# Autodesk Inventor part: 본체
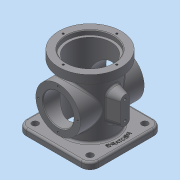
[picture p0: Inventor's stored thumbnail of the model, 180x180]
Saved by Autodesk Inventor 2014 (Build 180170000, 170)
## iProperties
Created: 2021-03
Part Number: 본체
Material: 일반
Document SubType Name: Modeling
Designer: net
Density: 1 g/cm^3
Appearance: 기본값
Author: net
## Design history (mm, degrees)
sketch "스케치1"
  geometry: L1 (-57, 57)-(57, 57); L2 (57, 57)-(57, -57); L3 (57, -57)-(-57, -57); L4 (-57, -57)-(-57, 57); 3 further points
  constraints: 8 end point, 2 midpoint, 2 parallel, 2 perpendicular, 1 horizontal, 1 horizontal alignment, 1 vertical alignment
  dimensions: "d0" = 114 distance of L3.end L1.start
extrude "돌출1" new body sketch "스케치1" distance "d1" = 10; taper "d2" = 0 deg
sketch "스케치2"
  geometry: L1 (57, 10)-(-57, 10) reference; L2 (49, 111)-(49, 98); L3 (49, 98)-(38, 98); L4 (38, 98)-(38, 10); L5 (33, 10)-(33, 104); L6 (33, 104)-(37, 104); L7 (37, 104)-(37, 111); L8 (0, 111)-(0, 10); L9 (49, 111)-(0, 111); L10 (-57, 0)-(57, 0) reference; L11 (38, 10)-(0, 10); 1 further point
  constraints: 18 end point, 3 point on line, 2 perpendicular, 1 collinear, 1 midpoint, 1 vertical alignment
  dimensions: "d4" = 7 distance between parallel lines of L6 L9; "d5" = 13 distance between parallel lines of L9 L3; "d6" = 98 diameter of L2 L8; "d7" = 74 diameter of L7 L8; "d8" = 66 diameter of L5 L8; "d9" = 76 diameter of L4 L8; "d11" = 104 distance between parallel lines of L10 L6
revolve "회전1" sketch "스케치2" stored, may be unused: angle "d10" = 90 deg
sketch "스케치3"
  geometry: L1 (-61.35, 54)-(61.35, 54); L2 (-57, 0)-(57, 0) reference; L3 (-50, 54)-(-50, 78); L4 (-50, 78)-(50, 78); L5 (50, 78)-(50, 54); L6 (50, 78)-(50, 89); L7 (50, 89)-(-50, 89); L8 (-50, 89)-(-50, 78); 4 further points
  constraints: 14 end point, 3 midpoint, 3 perpendicular, 2 parallel, 2 point on line, 2 vertical alignment, 1 collinear, 1 horizontal
  dimensions: "d12" = 54 distance between parallel lines of L2 L1; "d13" = 48 diameter of L4 L1; "d14" = 70 diameter of L7 L1; "d15" = 50 distance from line of L3 point (0, 54)
revolve "회전2" stored, may be unused: angle "d16" = 90 deg
revolve "회전3" stored, may be unused: angle "d17" = 90 deg
node "작업 평면1"
sketch "스케치4"
  geometry: L1 (0, 70)-(0, 41); L2 (-7, 70)-(-7, 41); L3 (7, 41)-(7, 70); L4 (0, 77)-(18.274, 77); L5 (0, 34)-(18.274, 34); L6 (0, 55.5)-(16.933, 55.5); L7 (-50, 30)-(-50, 78) reference; L8 (57, 0)-(-57, 0) reference; A1 r 7 centre (0, 70) between (7, 70) and (-7, 70); A2 r 7 centre (0, 41) between (-7, 41) and (7, 41); 3 further points
  constraints: 14 end point, 6 point on circle, 6 tangent, 3 midpoint, 3 parallel, 2 centre point, 1 perpendicular, 1 vertical, 1 vertical alignment
  dimensions: "d19" = 43 distance between parallel lines of L5 L4; "d20" = 20 vertical distance of L5.start point (-50, 54); "d21" = 14 distance between parallel lines of L3 L2
extrude "돌출2" join sketch "스케치4" stored distance "d22" = 10; taper "d23" = 15 deg
sketch "스케치5"
  geometry: C1 r 24 at (0, 0) reference; 2 further points
  constraints: 1 vertical alignment
hole "구멍1" sketch "스케치5" at (0, 31) diameter "d25" = 3.242; stored, may be unused: countersink angle "d29" = 90 deg, drill point angle "d31" = 118 deg; dims "d26" = 6, "d27" = 4, "d28" = 2, "d30" = 8
sketch "스케치6"
  geometry: C1 r 33 at (0, 0) reference
extrude "돌출3" cut sketch "스케치6" stored distance "d35" = 10; taper "d36" = 0 deg
fillet "모깎기1" dims "d37" = 14
sketch "스케치7"
  geometry: 1 further point
hole "구멍2" sketch "스케치7" at (0, 42) diameter "d39" = 3.242; stored, may be unused: countersink angle "d43" = 90 deg, drill point angle "d45" = 118 deg; dims "d40" = 6, "d41" = 4, "d42" = 2, "d44" = 8
sketch "스케치8"
  geometry: A1 r 7 centre (-41, 0) between (-41, -7) and (-41, 7) reference; A2 r 7 centre (-70, 0) between (-70, 7) and (-70, -7) reference; 1 further point
hole "구멍3" sketch "스케치8" at (-70, 0), (-41, 0) diameter "d49" = 4.134; stored, may be unused: countersink angle "d53" = 90 deg, drill point angle "d55" = 118 deg; dims "d50" = 8, "d51" = 4, "d52" = 2, "d54" = 10
sketch "스케치9"
  geometry: A1 r 14 centre (-43, 43) between (-43, 57) and (-57, 43) reference; A2 r 14 centre (-43, -43) between (-57, -43) and (-43, -57) reference; A3 r 14 centre (43, -43) between (43, -57) and (57, -43) reference; A4 r 14 centre (43, 43) between (57, 43) and (43, 57) reference
hole "구멍4" sketch "스케치9" at (43, -43), (-43, -43), (43, 43), (-43, 43) diameter "d56" = 10; stored, may be unused: countersink angle "d60" = 90 deg, drill point angle "d62" = 118 deg; dims "d57" = 8, "d58" = 4, "d59" = 2, "d61" = 10
chamfer "모따기1" distance "d63" = 1; stored, may be unused: second distance "d64" = 2, angle "d65" = 45 deg
fillet "모깎기2" dims "d66" = 3
sketch "스케치10"
  geometry: C1 r 41 at (0, 0) reference; C2 r 50 at (0, 0)
  constraints: 1 centre point, 1 coincident, 1 other
  dimensions: "d67" = 100 diameter of C2
feature "엠보싱1" sketch "스케치10" dims "d0" = 114, "d68" = 0.5, "d69" = 0
node "솔리드1"
pattern_circular "원형 패턴1" dims angle "d33" = 360 deg
mirror "대칭1"
pattern_circular "원형 패턴2" dims angle "d47" = 360 deg
other parameters: "d18" = 55
